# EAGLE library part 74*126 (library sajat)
Quad bus BUFFER, 3-state
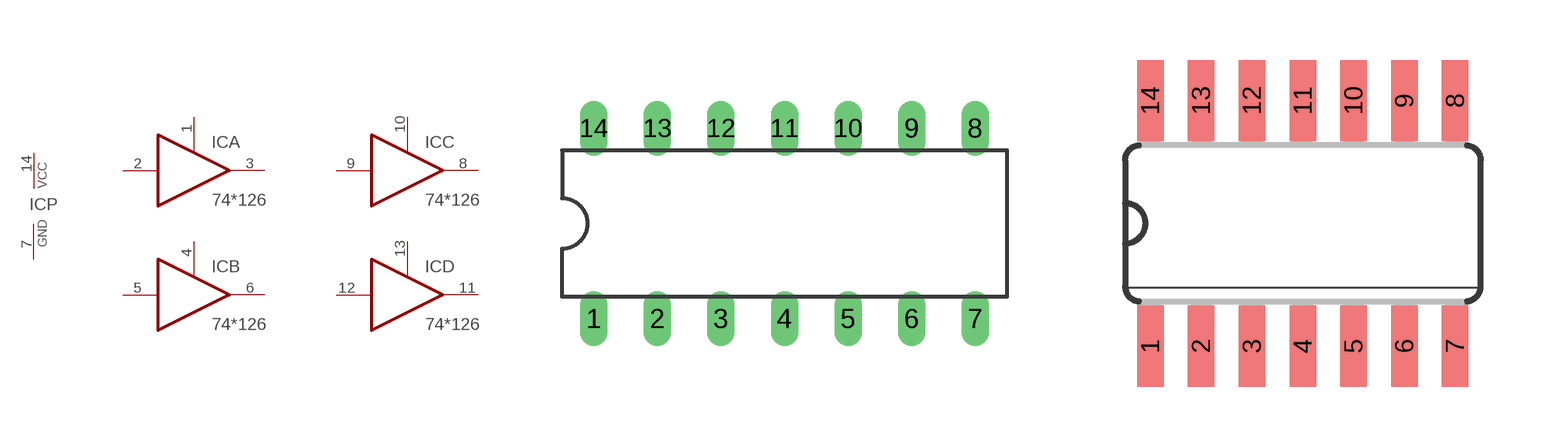
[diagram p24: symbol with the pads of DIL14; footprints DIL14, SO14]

Designator prefix IC; gates A=74126 B=74126 C=74126 D=74126 P=PWRN-1

## 74126N, 74AC126N, 74ACT126N, 74HC126N, 74HCT126N, 74LS126N  [DIL14]
1  A:OE  in
2  A:I  in
3  A:O  out
4  B:OE  in
5  B:I  in
6  B:O  out
7  P:GND  pwr
8  C:O  out
9  C:I  in
10  C:OE  in
11  D:O  out
12  D:I  in
13  D:OE  in
14  P:VCC  pwr

## 74AC126D, 74ACT126D, 74HC126D, 74HCT126D, 74LS126D  [SO14]
Pads as for DIL14

## 74AC126FK, 74ACT126FK, 74HC126FK, 74HCT126FK, 74LS126FK  [LCC20]
2  A:OE  in
3  A:I  in
4  A:O  out
6  B:OE  in
8  B:I  in
9  B:O  out
10  P:GND  pwr
12  C:O  out
13  C:I  in
14  C:OE  in
16  D:O  out
18  D:I  in
19  D:OE  in
20  P:VCC  pwr

## Footprint DIL14 (pad centres in mm)
Dual In Line Package
drill 0.6 pad 1.016 long: 1 -7.62,-3.81; 2 -5.08,-3.81; 3 -2.54,-3.81; 4 0,-3.81; 5 2.54,-3.81; 6 5.08,-3.81; 7 7.62,-3.81; 8 7.62,3.81; 9 5.08,3.81; 10 2.54,3.81; 11 0,3.81; 12 -2.54,3.81; 13 -5.08,3.81; 14 -7.62,3.81

## Footprint SO14 (pad centres in mm)
Small Outline package 150 mil
smd 0.66 x 2.032: 1 -3.81,-3.073; 2 -2.54,-3.073; 3 -1.27,-3.073; 4 0,-3.073; 5 1.27,-3.073; 6 2.54,-3.073; 7 3.81,-3.073; 8 3.81,3.073; 9 2.54,3.073; 10 1.27,3.073; 11 0,3.073; 12 -1.27,3.073; 13 -2.54,3.073; 14 -3.81,3.073

## Footprint LCC20 (pad centres in mm)
Leadless Chip Carrier Ceramic Package
smd 0.8 x 3.4: 1 0,3.8
smd 0.8 x 2: 2 -1.27,4.5; 3 -2.54,4.5; 9 -2.54,-4.5; 10 -1.27,-4.5; 11 0,-4.5; 12 1.27,-4.5; 13 2.54,-4.5; 19 2.54,4.5; 20 1.27,4.5
smd 2 x 0.8: 4 -4.5,2.54; 5 -4.5,1.27; 6 -4.5,0; 7 -4.5,-1.27; 8 -4.5,-2.54; 14 4.5,-2.54; 15 4.5,-1.27; 16 4.5,0; 17 4.5,1.27; 18 4.5,2.54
